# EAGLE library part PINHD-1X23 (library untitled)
PIN HEADER
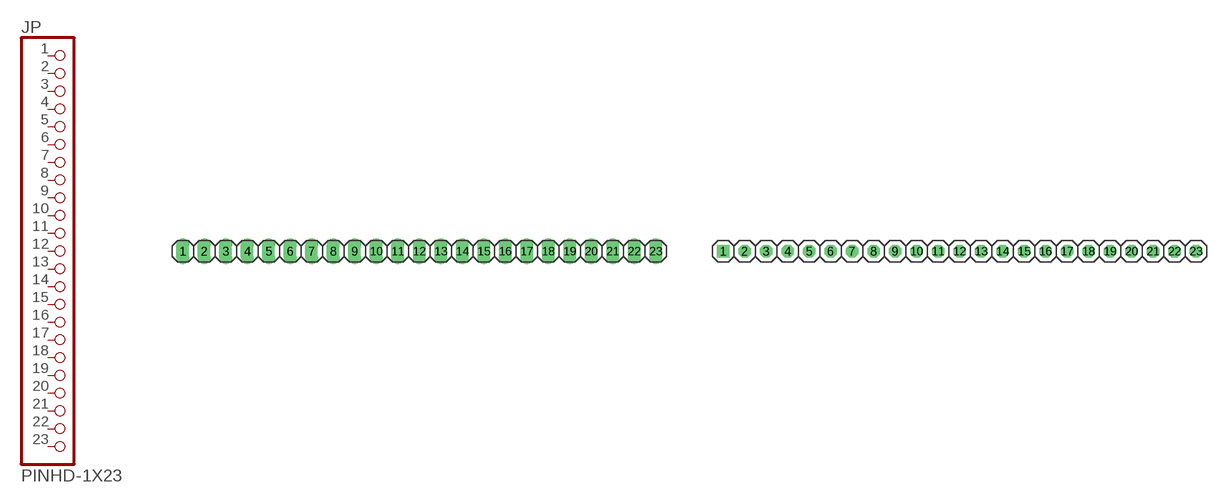
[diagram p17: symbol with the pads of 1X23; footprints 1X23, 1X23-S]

Designator prefix JP

## PINHD-1X23_2.54  [1X23]
1  1  pas
2  2  pas
3  3  pas
4  4  pas
5  5  pas
6  6  pas
7  7  pas
8  8  pas
9  9  pas
10  10  pas
11  11  pas
12  12  pas
13  13  pas
14  14  pas
15  15  pas
16  16  pas
17  17  pas
18  18  pas
19  19  pas
20  20  pas
21  21  pas
22  22  pas
23  23  pas

## PINHD-1X23_2.54-S  [1X23-S]
Pads as for 1X23

## PINHD-1X23_2.00  [1X23M]
Pads as for 1X23

## PINHD-1X23_2.54-90°  [1X23/90]
Pads as for 1X23

## PINHD-1X23_2.54-90°-S  [1X23/90-S]
Pads as for 1X23

## PINHD-1X23_2.54-SMD  [1X23SMD]
Pads as for 1X23

## PINHD-1X23_2.54-SMD-90°  [1X23SMD/90]
Pads as for 1X23

## Footprint 1X23 (pad centres in mm)
PIN HEADER - 2.54
drill 1.016 long: 1 -26.67,0; 2 -24.13,0; 3 -21.59,0; 4 -19.05,0; 5 -16.51,0; 6 -13.97,0; 7 -11.43,0; 8 -8.89,0; 9 -6.35,0; 10 -3.81,0; 11 -1.27,0; 12 1.27,0; 13 3.81,0; 14 6.35,0; 15 8.89,0; 16 11.43,0; 17 13.97,0; 18 16.51,0; 19 19.05,0; 20 21.59,0; 21 24.13,0; 22 26.67,0; 23 29.21,0

## Footprint 1X23-S (pad centres in mm)
PIN HEADER - 2.54
drill 1.016 square: 1 -26.67,0
drill 1.016 octagon: 2 -24.13,0; 3 -21.59,0; 4 -19.05,0; 5 -16.51,0; 6 -13.97,0; 7 -11.43,0; 8 -8.89,0; 9 -6.35,0; 10 -3.81,0; 11 -1.27,0; 12 1.27,0; 13 3.81,0; 14 6.35,0; 15 8.89,0; 16 11.43,0; 17 13.97,0; 18 16.51,0; 19 19.05,0; 20 21.59,0; 21 24.13,0; 22 26.67,0; 23 29.21,0

## Footprint 1X23M (pad centres in mm)
PIN HEADER - 2
drill 0.914 square: 1 -21,0
drill 0.914 round: 2 -19,0; 3 -17,0; 4 -15,0; 5 -13,0; 6 -11,0; 7 -9,0; 8 -7,0; 9 -5,0; 10 -3,0; 11 -1,0; 12 1,0; 13 3,0; 14 5,0; 15 7,0; 16 9,0; 17 11,0; 18 13,0; 19 15,0; 20 17,0; 21 19,0; 22 21,0; 23 23,0

## Footprint 1X23/90 (pad centres in mm)
PIN HEADER - 2.54 90°
drill 1.016 long: 1 -24.13,-3.81; 2 -21.59,-3.81; 3 -19.05,-3.81; 4 -16.51,-3.81; 5 -13.97,-3.81; 6 -11.43,-3.81; 7 -8.89,-3.81; 8 -6.35,-3.81; 9 -3.81,-3.81; 10 -1.27,-3.81; 11 1.27,-3.81; 12 3.81,-3.81; 13 6.35,-3.81; 14 8.89,-3.81; 15 11.43,-3.81; 16 13.97,-3.81; 17 16.51,-3.81; 18 19.05,-3.81; 19 21.59,-3.81; 20 24.13,-3.81; 21 26.67,-3.81; 22 29.21,-3.81; 23 31.75,-3.81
